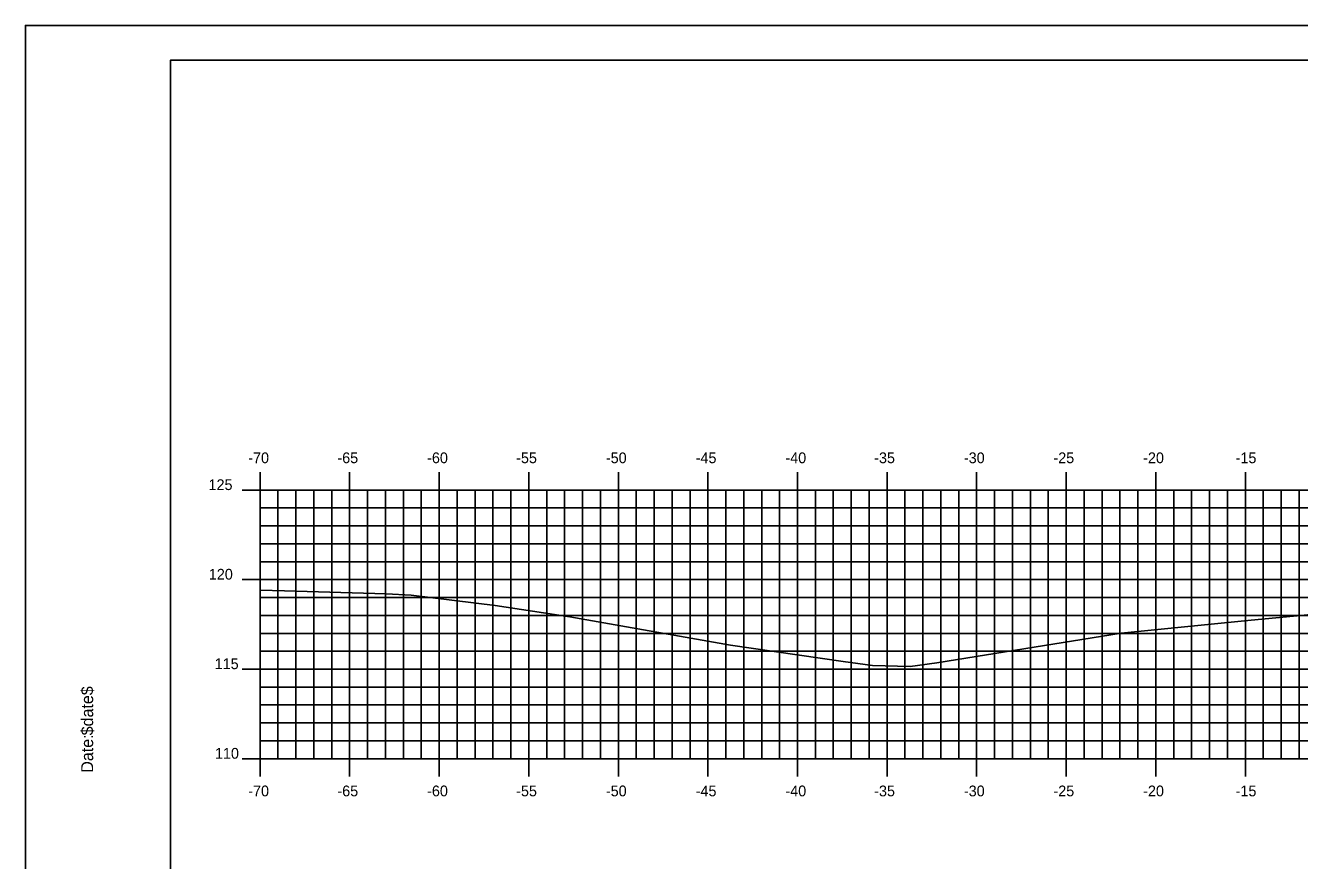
# Model space of a CAD drawing. Extents: x 853291 to 853462, y 365624 to 365734.
# Drawn here: x 853290.7 to 853361.8, y 365687.3 to 365734 of the extents above; entities that cross this region are included whole.
import ezdxf

# ---------------------------------------------------------------- set-up
doc = ezdxf.new("R2010")
doc.units = 0
for name, color, linetype in [('BORDER', 7, 'Continuous'), ('H_V ANNOTATION', 7, 'Continuous'), ('MAJOR', 7, 'Continuous'), ('MINOR', 7, 'Continuous'), ('PLOT BOUNDARY', 7, 'Continuous'), ('S_Roadway_Centerline', 7, 'Continuous')]:
    doc.layers.add(name, color=color, linetype=linetype)

msp = doc.modelspace()

# ---------------------------------------------------------------- linework, layer by layer
at = {"layer": 'BORDER'}
msp.add_lwpolyline([(853298.818, 365627.027), (853458.818, 365627.027), (853458.818, 365732.027), (853298.818, 365732.027)], close=True, dxfattribs=at)
at = {"layer": 'MAJOR'}
for p, q in [((853303.818, 365709.029), (853303.818, 365708.027)), ((853308.818, 365709.029), (853308.818, 365708.027)), ((853313.818, 365709.029), (853313.818, 365708.027)), ((853318.818, 365709.029), (853318.818, 365708.027)), ((853323.818, 365709.029), (853323.818, 365708.027)), ((853328.818, 365709.029), (853328.818, 365708.027)), ((853333.818, 365709.029), (853333.818, 365708.027)), ((853338.818, 365709.029), (853338.818, 365708.027)), ((853343.818, 365709.029), (853343.818, 365708.027)), ((853348.818, 365709.029), (853348.818, 365708.027)), ((853353.818, 365709.029), (853353.818, 365708.027)), ((853358.818, 365709.029), (853358.818, 365708.027)), ((853302.816, 365708.027), (853303.818, 365708.027)), ((853303.818, 365708.027), (853443.818, 365708.027)), ((853303.818, 365693.027), (853303.818, 365708.027)), ((853303.818, 365693.027), (853303.818, 365708.027)), ((853303.818, 365708.027), (853443.818, 365708.027)), ((853308.818, 365693.027), (853308.818, 365708.027)), ((853313.818, 365693.027), (853313.818, 365708.027)), ((853318.818, 365693.027), (853318.818, 365708.027)), ((853323.818, 365693.027), (853323.818, 365708.027)), ((853328.818, 365693.027), (853328.818, 365708.027)), ((853333.818, 365693.027), (853333.818, 365708.027)), ((853338.818, 365693.027), (853338.818, 365708.027)), ((853343.818, 365693.027), (853343.818, 365708.027)), ((853348.818, 365693.027), (853348.818, 365708.027)), ((853353.818, 365693.027), (853353.818, 365708.027)), ((853358.818, 365693.027), (853358.818, 365708.027)), ((853302.816, 365703.027), (853303.818, 365703.027)), ((853303.818, 365703.027), (853443.818, 365703.027)), ((853302.816, 365698.027), (853303.818, 365698.027)), ((853303.818, 365698.027), (853443.818, 365698.027)), ((853302.816, 365693.027), (853303.818, 365693.027)), ((853303.818, 365693.027), (853443.818, 365693.027)), ((853303.818, 365693.027), (853443.818, 365693.027)), ((853303.818, 365692.025), (853303.818, 365693.027)), ((853308.818, 365692.025), (853308.818, 365693.027)), ((853313.818, 365692.025), (853313.818, 365693.027)), ((853318.818, 365692.025), (853318.818, 365693.027)), ((853323.818, 365692.025), (853323.818, 365693.027)), ((853328.818, 365692.025), (853328.818, 365693.027)), ((853333.818, 365692.025), (853333.818, 365693.027)), ((853338.818, 365692.025), (853338.818, 365693.027)), ((853343.818, 365692.025), (853343.818, 365693.027)), ((853348.818, 365692.025), (853348.818, 365693.027)), ((853353.818, 365692.025), (853353.818, 365693.027)), ((853358.818, 365692.025), (853358.818, 365693.027))]:
    msp.add_line(p, q, dxfattribs=at)
at = {"layer": 'MINOR'}
for p, q in [((853304.818, 365693.027), (853304.818, 365708.027)), ((853305.818, 365693.027), (853305.818, 365708.027)), ((853306.818, 365693.027), (853306.818, 365708.027)), ((853307.818, 365693.027), (853307.818, 365708.027)), ((853309.818, 365693.027), (853309.818, 365708.027)), ((853310.818, 365693.027), (853310.818, 365708.027)), ((853311.818, 365693.027), (853311.818, 365708.027)), ((853312.818, 365693.027), (853312.818, 365708.027)), ((853314.818, 365693.027), (853314.818, 365708.027)), ((853315.818, 365693.027), (853315.818, 365708.027)), ((853316.818, 365693.027), (853316.818, 365708.027)), ((853317.818, 365693.027), (853317.818, 365708.027)), ((853319.818, 365693.027), (853319.818, 365708.027)), ((853320.818, 365693.027), (853320.818, 365708.027)), ((853321.818, 365693.027), (853321.818, 365708.027)), ((853322.818, 365693.027), (853322.818, 365708.027)), ((853324.818, 365693.027), (853324.818, 365708.027)), ((853325.818, 365693.027), (853325.818, 365708.027)), ((853326.818, 365693.027), (853326.818, 365708.027)), ((853327.818, 365693.027), (853327.818, 365708.027)), ((853329.818, 365693.027), (853329.818, 365708.027)), ((853330.818, 365693.027), (853330.818, 365708.027)), ((853331.818, 365693.027), (853331.818, 365708.027)), ((853332.818, 365693.027), (853332.818, 365708.027)), ((853334.818, 365693.027), (853334.818, 365708.027)), ((853335.818, 365693.027), (853335.818, 365708.027)), ((853336.818, 365693.027), (853336.818, 365708.027)), ((853337.818, 365693.027), (853337.818, 365708.027)), ((853339.818, 365693.027), (853339.818, 365708.027)), ((853340.818, 365693.027), (853340.818, 365708.027)), ((853341.818, 365693.027), (853341.818, 365708.027)), ((853342.818, 365693.027), (853342.818, 365708.027)), ((853344.818, 365693.027), (853344.818, 365708.027)), ((853345.818, 365693.027), (853345.818, 365708.027)), ((853346.818, 365693.027), (853346.818, 365708.027)), ((853347.818, 365693.027), (853347.818, 365708.027)), ((853349.818, 365693.027), (853349.818, 365708.027)), ((853350.818, 365693.027), (853350.818, 365708.027)), ((853351.818, 365693.027), (853351.818, 365708.027)), ((853352.818, 365693.027), (853352.818, 365708.027)), ((853354.818, 365693.027), (853354.818, 365708.027)), ((853355.818, 365693.027), (853355.818, 365708.027)), ((853356.818, 365693.027), (853356.818, 365708.027)), ((853357.818, 365693.027), (853357.818, 365708.027)), ((853359.818, 365693.027), (853359.818, 365708.027)), ((853360.818, 365693.027), (853360.818, 365708.027)), ((853361.818, 365693.027), (853361.818, 365708.027)), ((853303.818, 365707.027), (853443.818, 365707.027)), ((853303.818, 365707.027), (853304.82, 365707.027)), ((853303.818, 365706.027), (853443.818, 365706.027)), ((853303.818, 365706.027), (853304.82, 365706.027)), ((853303.818, 365705.027), (853443.818, 365705.027)), ((853303.818, 365705.027), (853304.82, 365705.027)), ((853303.818, 365704.027), (853443.818, 365704.027)), ((853303.818, 365704.027), (853304.82, 365704.027)), ((853303.818, 365702.027), (853443.818, 365702.027)), ((853303.818, 365702.027), (853304.82, 365702.027)), ((853303.818, 365701.027), (853443.818, 365701.027)), ((853303.818, 365701.027), (853304.82, 365701.027)), ((853303.818, 365700.027), (853443.818, 365700.027)), ((853303.818, 365700.027), (853304.82, 365700.027)), ((853303.818, 365699.027), (853443.818, 365699.027)), ((853303.818, 365699.027), (853304.82, 365699.027)), ((853303.818, 365697.027), (853443.818, 365697.027)), ((853303.818, 365697.027), (853304.82, 365697.027)), ((853303.818, 365696.027), (853443.818, 365696.027)), ((853303.818, 365696.027), (853304.82, 365696.027)), ((853303.818, 365695.027), (853443.818, 365695.027)), ((853303.818, 365695.027), (853304.82, 365695.027)), ((853303.818, 365694.027), (853443.818, 365694.027)), ((853303.818, 365694.027), (853304.82, 365694.027))]:
    msp.add_line(p, q, dxfattribs=at)
at = {"layer": 'PLOT BOUNDARY'}
msp.add_lwpolyline([(853290.725, 365623.968), (853460.725, 365623.968), (853460.725, 365733.968), (853290.725, 365733.968)], close=True, dxfattribs=at)
at = {"layer": 'S_Roadway_Centerline'}
msp.add_lwpolyline([(853303.818, 365702.431), (853305.19, 365702.4), (853310.863, 365702.235), (853312.251, 365702.165), (853316.934, 365701.576), (853321.101, 365700.956), (853330.083, 365699.363), (853336.373, 365698.45), (853338.007, 365698.223), (853340.115, 365698.168), (853341.589, 365698.376), (853351.88, 365700.031), (853359.138, 365700.764), (853367.599, 365701.559)], dxfattribs=at)

# ---------------------------------------------------------------- texts
at = {"layer": 'BORDER'}
for s, p in [('$date$', (853294.503, 365694.332)), ('Date:', (853294.503, 365692.244))]:
    msp.add_text(s, height=0.6696, rotation=90, dxfattribs=at).set_placement(p)
at = {"layer": 'H_V ANNOTATION'}
for s, p in [('-70', (853303.16, 365709.527)), ('-65', (853308.136, 365709.527)), ('-60', (853313.144, 365709.527)), ('-55', (853318.114, 365709.527)), ('-50', (853323.122, 365709.527)), ('-45', (853328.136, 365709.527)), ('-40', (853333.144, 365709.527)), ('-35', (853338.098, 365709.527)), ('-30', (853343.106, 365709.527)), ('-25', (853348.104, 365709.527)), ('-20', (853353.112, 365709.527)), ('-15', (853358.275, 365709.527)), ('125', (853300.943, 365708.027)), ('120', (853300.959, 365703.027)), ('115', (853301.285, 365698.027)), ('110', (853301.301, 365693.027)), ('-70', (853303.16, 365690.927)), ('-65', (853308.136, 365690.927)), ('-60', (853313.144, 365690.927)), ('-55', (853318.114, 365690.927)), ('-50', (853323.122, 365690.927)), ('-45', (853328.136, 365690.927)), ('-40', (853333.144, 365690.927)), ('-35', (853338.098, 365690.927)), ('-30', (853343.106, 365690.927)), ('-25', (853348.104, 365690.927)), ('-20', (853353.112, 365690.927)), ('-15', (853358.275, 365690.927))]:
    msp.add_text(s, height=0.6, dxfattribs=at).set_placement(p)
at = {"layer": 'MAJOR'}
msp.add_text('-', height=0.006, dxfattribs=at).set_placement((853303.814, 365693.027))

doc.saveas('drawing.dxf')
